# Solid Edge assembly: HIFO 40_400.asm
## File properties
Title: Zylinder
Author: ahadarics
Template: iso assembly.asm
Last saved by: ahadarics
Revision: 47
Application: Solid Edge
Username: ahadarics
Dokumentum tartalom típus: 1
Document Number: HIFO 40/400
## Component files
Profilrohr 40_400.par
Mutter.par
Kolbenstange 40_400.par
Kit_1.par
Kit_2.par
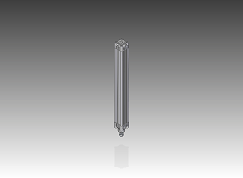
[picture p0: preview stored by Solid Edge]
